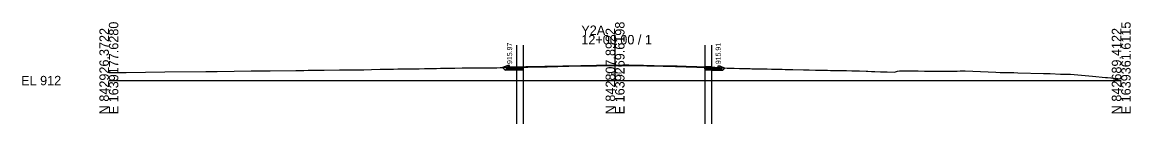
# Model space of a CAD drawing. Extents: x -26 to 303, y -10 to 10517.
# Drawn here: x -25.7 to 302.8, y 1487.2 to 1517.3 of the extents above; entities that cross this region are included whole.
import ezdxf

# ---------------------------------------------------------------- set-up
doc = ezdxf.new("R2010")
doc.units = 0
for name, color, linetype in [('Exist Cross Section Cell', 7, 'Continuous'), ('Exist XS Center Line Elevation Label', 7, 'Continuous'), ('Exist XS Ground Line', 7, 'Continuous'), ('Prop CMT Conc Surface', 7, 'Continuous'), ('Prop CMT Concrete Structures', 7, 'Continuous'), ('Prop CMT Pvmt Course 1', 7, 'Continuous'), ('Prop CMT Pvmt Course 1 CG', 7, 'Continuous'), ('Prop CMT Pvmt Course 2', 7, 'Continuous'), ('Prop CMT Pvmt Surface Overlay', 7, 'Continuous'), ('Prop CMT Slope Grass', 7, 'Continuous'), ('Prop CMT Subgrade Earthwork', 7, 'Continuous'), ('Prop XS Hydro Elevations', 7, 'Continuous'), ('Scratch_Level_0', 7, 'Continuous'), ('Scratch_Level_2', 7, 'Continuous')]:
    doc.layers.add(name, color=color, linetype=linetype)

msp = doc.modelspace()

# ---------------------------------------------------------------- linework, layer by layer
at = {"layer": 'Exist Cross Section Cell'}
for p, q in [((150, 1500), (150, 1513.53)), ((0, 1500), (150, 1500)), ((150, 1500), (300, 1500))]:
    msp.add_line(p, q, dxfattribs=at)
at = {"layer": 'Exist XS Ground Line'}
msp.add_lwpolyline([(0, 1502.38), (0.97, 1502.39), (1.5, 1502.38), (1.9, 1502.39), (5.12, 1502.43), (16.61, 1502.55), (28.75, 1502.72), (29.22, 1502.72), (29.73, 1502.72), (30.27, 1502.72), (30.85, 1502.73), (31.46, 1502.74), (32.12, 1502.74), (42.14, 1502.88), (42.94, 1502.89), (43.78, 1502.89), (44.68, 1502.9), (45.65, 1502.91), (46.69, 1502.92), (47.82, 1502.93), (55.38, 1503), (56.52, 1503), (57.75, 1503.03), (59.07, 1503.04), (60.5, 1503.05), (62.06, 1503.07), (63.75, 1503.09), (68.39, 1503.16), (69.94, 1503.18), (71.62, 1503.2), (73.44, 1503.23), (75.53, 1503.23), (77.83, 1503.26), (80.39, 1503.34), (80.95, 1503.35), (83.42, 1503.38), (84.36, 1503.42), (85.63, 1503.46), (85.97, 1503.48), (86.66, 1503.46), (88.28, 1503.46), (89.08, 1503.46), (91.94, 1503.47), (93.54, 1503.57), (95.59, 1503.59), (97.1, 1503.61), (98.27, 1503.66), (98.59, 1503.66), (99.66, 1503.66), (100.66, 1503.64), (101.44, 1503.68), (102.55, 1503.71), (104.65, 1503.74), (105.08, 1503.75), (105.79, 1503.75), (107.16, 1503.76), (107.82, 1503.75), (109.67, 1503.77), (110.93, 1503.8), (111.83, 1503.8), (112.99, 1503.8), (114.1, 1503.82), (114.92, 1503.83), (115.97, 1503.84), (116.7, 1503.85), (117.26, 1503.86), (120.05, 1503.99), (120.43, 1504.01), (122.04, 1504), (123.59, 1504), (124.12, 1504.01), (126.76, 1504.06), (128.2, 1504.09), (129.17, 1504.1), (129.92, 1504.12), (130.95, 1504.14), (132.28, 1504.17), (132.73, 1504.19), (133.09, 1504.19), (134.52, 1504.23), (136.35, 1504.26), (139.42, 1504.33), (139.86, 1504.34), (140.43, 1504.34), (142.58, 1504.37), (143.42, 1504.4), (144.51, 1504.41), (145.21, 1504.43), (145.75, 1504.43), (146.99, 1504.44), (148.58, 1504.46), (148.91, 1504.46), (150.07, 1504.48), (152.33, 1504.51), (152.66, 1504.51), (154.11, 1504.5), (155.24, 1504.49), (155.9, 1504.48), (156.73, 1504.47), (157.68, 1504.46), (158.41, 1504.43), (159.46, 1504.4), (160.81, 1504.38), (161.57, 1504.36), (164.23, 1504.3), (164.89, 1504.28), (166.59, 1504.23), (167.9, 1504.21), (168.37, 1504.2), (168.96, 1504.18), (171.07, 1504.12), (171.93, 1504.09), (173.04, 1504.06), (173.71, 1504.04), (174.23, 1504.02), (177.4, 1503.91), (178.38, 1503.87), (180.84, 1503.75), (181.19, 1503.75), (183.18, 1503.69), (183.97, 1503.66), (185.27, 1503.64), (186.9, 1503.61), (187.97, 1503.58), (189.35, 1503.55), (190.05, 1503.54), (190.52, 1503.53), (193.42, 1503.46), (195.09, 1503.44), (196.39, 1503.41), (197.5, 1503.39), (198.66, 1503.37), (199.56, 1503.34), (200.44, 1503.31), (201.58, 1503.29), (202.22, 1503.28), (202.72, 1503.26), (205.89, 1503.19), (207.57, 1503.15), (209.35, 1503.11), (209.73, 1503.1), (211.13, 1503.09), (212.22, 1503.06), (212.91, 1503.04), (213.8, 1503.03), (215.38, 1503), (217.88, 1502.97), (218.55, 1502.96), (220.12, 1502.9), (221.88, 1502.88), (222.42, 1502.86), (224.43, 1502.79), (224.94, 1502.78), (225.99, 1502.72), (226.98, 1502.68), (228.63, 1502.63), (229.72, 1502.59), (230.59, 1502.56), (232.81, 1502.48), (233.7, 1502.75), (234.29, 1502.92), (235.41, 1502.91), (237.72, 1502.88), (239.82, 1502.86), (241.72, 1502.84), (244.5, 1502.84), (246.32, 1502.83), (247.92, 1502.83), (249.26, 1502.83), (250.39, 1502.83), (251.37, 1502.83), (252.26, 1502.85), (253.03, 1502.86), (253.7, 1502.88), (262.82, 1502.48), (264.12, 1502.44), (265.76, 1502.4), (266.92, 1502.37), (268.19, 1502.35), (269.36, 1502.34), (276.93, 1502.08), (277.48, 1502.07), (277.99, 1502.06), (278.46, 1502.06), (278.89, 1502.05), (282.01, 1501.94), (284.99, 1501.86), (291.45, 1501.34), (295.37, 1500.94), (295.88, 1500.89), (300, 1500.53)], dxfattribs=at)
at = {"layer": 'Prop CMT Conc Surface'}
for points in [[(118.75, 1503.97), (118.75, 1504.47), (118.25, 1504.47)], [(180.56, 1503.91), (180.56, 1504.41), (181.06, 1504.41)]]:
    msp.add_lwpolyline(points, dxfattribs=at)
at = {"layer": 'Prop CMT Concrete Structures'}
for points in [[(120.75, 1504.09), (118.75, 1503.97), (118.75, 1504.47), (118.25, 1504.47)], [(118.25, 1504.47), (118.25, 1503.45), (120.75, 1503.5)], [(178.56, 1504.03), (180.56, 1503.91), (180.56, 1504.41), (181.06, 1504.41)], [(181.06, 1504.41), (181.06, 1503.4), (178.56, 1503.45)]]:
    msp.add_lwpolyline(points, dxfattribs=at)
at = {"layer": 'Prop CMT Pvmt Course 1'}
for p, q in [((120.75, 1504.09), (122.75, 1504.12)), ((120.75, 1504.09), (120.75, 1503.84)), ((120.75, 1503.84), (122.75, 1503.87)), ((122.75, 1504.12), (122.75, 1503.87)), ((176.56, 1504.07), (176.56, 1503.82)), ((178.56, 1504.03), (176.56, 1504.07)), ((178.56, 1503.78), (176.56, 1503.82)), ((178.56, 1504.03), (178.56, 1503.78))]:
    msp.add_line(p, q, dxfattribs=at)
at = {"layer": 'Prop CMT Pvmt Course 1 CG'}
for p, q in [((120.75, 1503.51), (120.75, 1503.17)), ((120.75, 1503.17), (122.75, 1503.21)), ((122.75, 1503.54), (122.75, 1503.21)), ((176.56, 1503.49), (176.56, 1503.15)), ((178.56, 1503.12), (176.56, 1503.15)), ((178.56, 1503.45), (178.56, 1503.12))]:
    msp.add_line(p, q, dxfattribs=at)
for points in [[(120.75, 1503.5), (117.75, 1503.44), (117.41, 1503.11)], [(117.45, 1503.11), (120.75, 1503.17)], [(178.56, 1503.45), (181.56, 1503.39), (181.9, 1503.05)], [(181.86, 1503.05), (178.56, 1503.12)]]:
    msp.add_lwpolyline(points, dxfattribs=at)
at = {"layer": 'Prop CMT Pvmt Course 2'}
for p, q in [((120.75, 1503.51), (120.75, 1503.84)), ((120.75, 1503.51), (122.75, 1503.54)), ((122.75, 1503.54), (122.75, 1503.87)), ((176.56, 1503.49), (176.56, 1503.82)), ((178.56, 1503.45), (176.56, 1503.49)), ((178.56, 1503.45), (178.56, 1503.78))]:
    msp.add_line(p, q, dxfattribs=at)
at = {"layer": 'Prop CMT Pvmt Surface Overlay'}
msp.add_lwpolyline([(122.75, 1504.12), (123.59, 1504.13), (124.12, 1504.14), (126.76, 1504.19), (128.2, 1504.22), (129.17, 1504.23), (129.92, 1504.25), (130.95, 1504.27), (132.27, 1504.3), (132.73, 1504.31), (133.09, 1504.32), (134.51, 1504.36), (136.35, 1504.38), (139.86, 1504.46), (140.43, 1504.47), (142.58, 1504.5), (143.42, 1504.52), (144.5, 1504.54), (145.2, 1504.55), (145.75, 1504.55), (146.99, 1504.56), (148.58, 1504.58), (148.91, 1504.59), (150.07, 1504.6), (152.33, 1504.63), (152.66, 1504.63), (154.12, 1504.63), (155.25, 1504.61), (155.9, 1504.61), (156.74, 1504.59), (157.68, 1504.58), (158.41, 1504.56), (159.46, 1504.52), (160.81, 1504.5), (161.58, 1504.48), (164.23, 1504.42), (164.89, 1504.4), (166.59, 1504.36), (167.91, 1504.33), (168.37, 1504.33), (168.97, 1504.31), (171.07, 1504.25), (171.94, 1504.22), (173.04, 1504.18), (173.72, 1504.16), (174.24, 1504.14), (176.56, 1504.07)], dxfattribs=at)
at = {"layer": 'Prop CMT Slope Grass'}
for points in [[(118.25, 1504.47), (116.68, 1503.85)], [(181.06, 1504.41), (182.55, 1503.71)]]:
    msp.add_lwpolyline(points, dxfattribs=at)
at = {"layer": 'Prop CMT Subgrade Earthwork'}
for points in [[(120.75, 1503.17), (117.41, 1503.11), (116.68, 1503.85)], [(178.56, 1503.12), (181.9, 1503.05), (182.55, 1503.71)]]:
    msp.add_lwpolyline(points, dxfattribs=at)
at = {"layer": 'Scratch_Level_0'}
for p, q in [((120.75, 1510.5), (120.75, 1487.16)), ((122.75, 1510.5), (122.75, 1487.16)), ((176.56, 1510.5), (176.56, 1487.16)), ((178.56, 1510.5), (178.56, 1487.16))]:
    msp.add_line(p, q, dxfattribs=at)
at = {"layer": 'Scratch_Level_2'}
for p, q in [((122.75, 1504), (122.04, 1504)), ((182.55, 1503.71), (181.19, 1503.75))]:
    msp.add_line(p, q, dxfattribs=at)
for points in [[(122.04, 1504), (120.43, 1504.01), (120.05, 1503.99), (117.26, 1503.86), (116.7, 1503.85), (116.68, 1503.85)], [(122.75, 1504), (122.75, 1503.21), (120.75, 1503.17), (117.41, 1503.11), (116.68, 1503.85)], [(116.68, 1503.85), (117.41, 1503.11), (120.75, 1503.17), (122.75, 1503.21), (122.75, 1504)], [(176.56, 1503.94), (176.56, 1503.15), (178.56, 1503.12), (181.9, 1503.05), (182.55, 1503.71)], [(181.19, 1503.75), (180.84, 1503.75), (178.38, 1503.87), (177.4, 1503.91), (176.56, 1503.94)], [(176.56, 1503.94), (176.56, 1503.15), (178.56, 1503.12), (181.9, 1503.05), (182.55, 1503.71)]]:
    msp.add_lwpolyline(points, dxfattribs=at)

# ---------------------------------------------------------------- texts
at = {"layer": 'Exist Cross Section Cell'}
for s, p in [('N 842926.3722', (0, 1490)), ('E 1639177.6280', (2.8, 1490)), ('N 842807.8922', (150, 1490)), ('E 1639269.6198', (152.8, 1490)), ('N 842689.4122', (300, 1490)), ('E 1639361.6115', (302.8, 1490))]:
    msp.add_text(s, height=2.8, rotation=90, dxfattribs=at).set_placement(p)
for s, p in [('Y2A', (140, 1513.53)), ('12+00.00 / 1', (140, 1510.73)), ('EL 912', (-26, 1498.6))]:
    msp.add_text(s, height=2.8, dxfattribs=at).set_placement(p)
at = {"layer": 'Exist XS Center Line Elevation Label'}
msp.add_text('916.48', height=1, dxfattribs=at).set_placement((147.71, 1501.58))
at = {"layer": 'Prop XS Hydro Elevations'}
for s, p in [('915.97', (119.5, 1504.92)), ('915.91', (181.31, 1504.87))]:
    msp.add_text(s, height=1.5, rotation=90, dxfattribs=at).set_placement(p)

doc.saveas('drawing.dxf')
